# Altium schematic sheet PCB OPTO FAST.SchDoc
size A
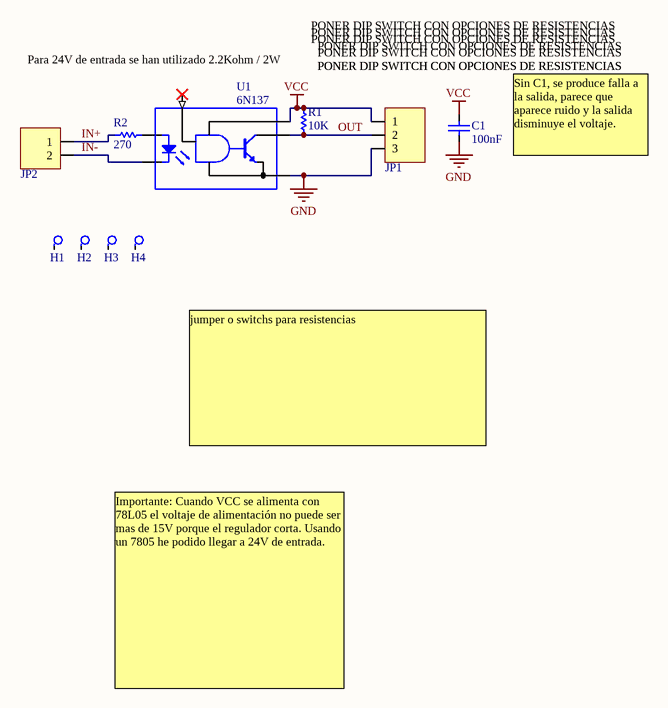
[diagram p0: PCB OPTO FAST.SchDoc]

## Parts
C1  Capacidad: 100nF  [C1206]  (hidden comment: Capacitor 1206; 100nF; 50V)
H1  Agujero de Montaje  [agujero]  (value not drawn)  (no BOM)
H2  Agujero de Montaje  [agujero]  (value not drawn)  (no BOM)
H3  Agujero de Montaje  [agujero]  (value not drawn)  (no BOM)
H4  Agujero de Montaje  [agujero]  (value not drawn)  (no BOM)
JP1  Header3x1  [conpol3x1]  (value not drawn)
JP2  Header2x1  [CONPOL2X1]  (value not drawn)
R1  value 10K  [R1206]  (hidden comment: Res)
R2  value 270  [R1206]  (hidden comment: Res)
U1  6N137  [DIP8Z]

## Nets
GND: C1.1 JP1.3 U1.5(GND)
VCC: C1.2 JP1.1 R1.2 U1.8(VCC)
IN+: JP2.1 R2.1
IN-: JP2.2 U1.3(K)
OUT: JP1.2 R1.1 U1.6(VO)
NetR2_2: R2.2 U1.2(A)

Not connected (* = marked no-connect by the designer): H1 1; H2 1; H3 1; H4 1; U1 7(VE)*

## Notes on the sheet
- Para 24V de entrada se han utilizado 2.2Kohm / 2W
- PONER DIP SWITCH CON OPCIONES DE RESISTENCIAS
- Sin C1, se produce falla a la salida, parece que aparece ruido y la salida disminuye el voltaje.
- jumper o switchs para resistencias
- Importante: Cuando VCC se alimenta con 78L05 el voltaje de alimentación no puede ser mas de 15V porque el regulador corta. Usando un 7805 he podido llegar a 24V de entrada.

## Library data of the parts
C1 = Capacitor 1206; 100nF; 50V: Dolares Elemon: 0.03125; Codigo Elemon: CA3269770K
JP1 = Header3x1: Header 3x1
JP2 = Header2x1: Header 2x1
R1 R2 = Res: Resistor; Power: 0.25W
U1 = 6N137: Optoaislador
